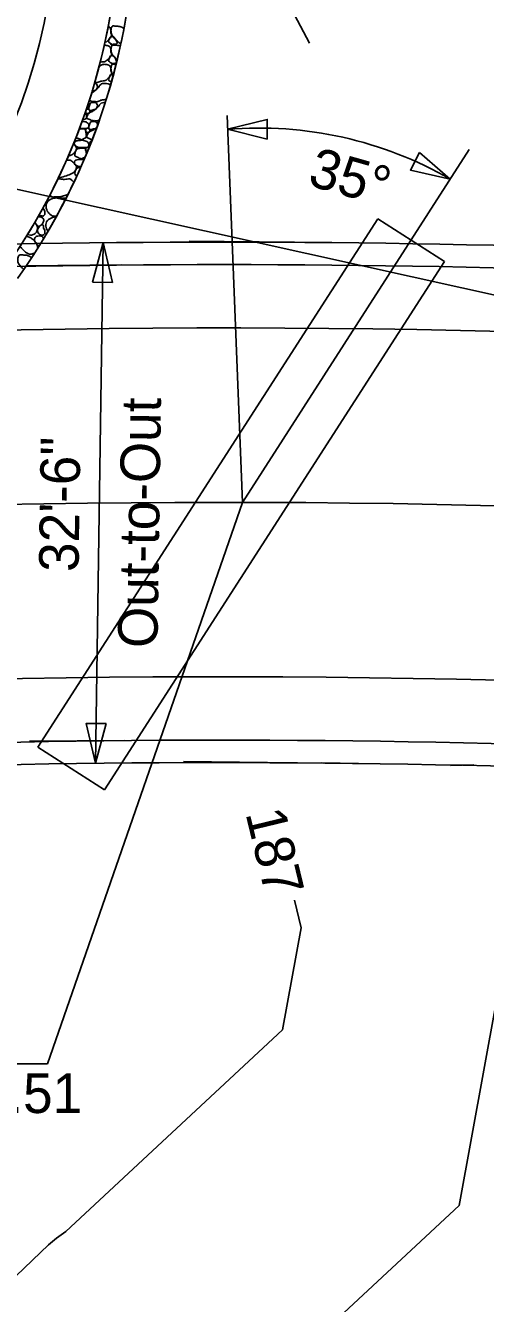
# Model space of a CAD drawing. Extents: x 1385284 to 1385995, y 1975154 to 1975620.
# Drawn here: x 1385501.9 to 1385530.9, y 1975439 to 1975519.6 of the extents above; entities that cross this region are included whole.
import ezdxf

# ---------------------------------------------------------------- set-up
doc = ezdxf.new("R2010")
doc.units = 0
for name, color, linetype in [('Default', 7, 'Continuous'), ('DTM_CONTOURS_MINOR', 7, 'Continuous'), ('R_Bridge', 7, 'Continuous'), ('R_Horz Alg', 7, 'Continuous'), ('R_Horz Alg Annot', 7, 'Continuous'), ('R_Proposed Const Limits', 7, 'Continuous'), ('R_Proposed Road', 7, 'Continuous')]:
    doc.layers.add(name, color=color, linetype=linetype)

msp = doc.modelspace()

# ---------------------------------------------------------------- linework, layer by layer
at = {"layer": 'Default'}
for p, q in [((1385514.615, 1975513.961), (1385515.576, 1975489.559)), ((1385515.576, 1975489.559), (1385529.884, 1975511.809)), ((1385502.679, 1975474.127), (1385524.111, 1975507.453)), ((1385524.111, 1975507.453), (1385528.316, 1975504.748)), ((1385506.801, 1975505.941), (1385506.327, 1975473.111)), ((1385521.062, 1975505.947), (1385512.231, 1975506.045)), ((1385507.954, 1975504.533), (1385501.951, 1975504.489)), ((1385506.884, 1975471.422), (1385528.316, 1975504.748)), ((1385515.576, 1975489.559), (1385503.294, 1975454.146)), ((1385508.172, 1975474.533), (1385502.168, 1975474.49)), ((1385502.679, 1975474.127), (1385506.884, 1975471.422)), ((1385520.694, 1975473.115), (1385511.864, 1975473.214)), ((1385522.895, 1975473.091), (1385520.589, 1975473.124)), ((1385530.16, 1975472.995), (1385528.688, 1975472.97)), ((1385503.294, 1975454.146), (1385480.831, 1975454.146))]:
    msp.add_line(p, q, dxfattribs=at)
for points in [[(1385517.149, 1975512.468), (1385514.649, 1975513.093), (1385517.149, 1975513.718)], [(1385526.741, 1975511.636), (1385528.686, 1975509.946), (1385526.175, 1975510.522)], [(1385506.14, 1975503.45), (1385506.801, 1975505.941), (1385507.39, 1975503.432)], [(1385506.988, 1975475.601), (1385506.327, 1975473.111), (1385505.739, 1975475.619)]]:
    msp.add_lwpolyline(points, close=True, dxfattribs=at)
for centre, radius, start, end in [((1385468.803, 1975526.863), 40, 324.56338, 101.99838), ((1385468.803, 1975526.863), 39, 324.56338, 101.99838), ((1385468.803, 1975526.863), 40, 324.56338, 46.11578), ((1385468.803, 1975526.863), 39, 324.56338, 45.8751), ((1385516.608, 1975488.949), 24.223, 60.09033, 94.63843)]:
    msp.add_arc(centre, radius, start, end, dxfattribs=at)
for points in [[(1385507.11, 1975519.581), (1385507.151, 1975519.575), (1385507.288, 1975519.487), (1385507.282, 1975519.271), (1385507.368, 1975518.96), (1385507.154, 1975518.753), (1385507.012, 1975518.6), (1385506.911, 1975518.569), (1385506.883, 1975518.563)], [(1385507.894, 1975518.503), (1385507.885, 1975518.508), (1385507.786, 1975518.568), (1385507.632, 1975518.71), (1385507.422, 1975518.934), (1385507.263, 1975519.174), (1385507.296, 1975519.4), (1385507.366, 1975519.642), (1385507.595, 1975519.589), (1385507.86, 1975519.595), (1385508.031, 1975519.509), (1385508.108, 1975519.463)], [(1385506.845, 1975518.391), (1385506.92, 1975518.401), (1385507.046, 1975518.381), (1385507.289, 1975518.296), (1385507.282, 1975518.068), (1385507.368, 1975517.757), (1385507.154, 1975517.55), (1385506.932, 1975517.327), (1385506.72, 1975517.351), (1385506.605, 1975517.315), (1385506.604, 1975517.315)], [(1385507.4, 1975518.447), (1385507.353, 1975518.446), (1385507.257, 1975518.519), (1385507.094, 1975518.612), (1385507.203, 1975518.797), (1385507.251, 1975518.962), (1385507.432, 1975518.936), (1385507.552, 1975518.831), (1385507.619, 1975518.687), (1385507.806, 1975518.438), (1385507.056, 1975518.455), (1385507.442, 1975518.444), (1385507.434, 1975518.447)], [(1385507.665, 1975517.481), (1385507.661, 1975517.486), (1385507.576, 1975517.57), (1385507.422, 1975517.731), (1385507.263, 1975517.971), (1385507.296, 1975518.197), (1385507.366, 1975518.439), (1385507.593, 1975518.387), (1385507.757, 1975518.383), (1385507.862, 1975518.363)], [(1385507.4, 1975517.244), (1385507.353, 1975517.243), (1385507.257, 1975517.316), (1385507.094, 1975517.409), (1385507.203, 1975517.594), (1385507.251, 1975517.759), (1385507.432, 1975517.733), (1385507.552, 1975517.628), (1385507.607, 1975517.496), (1385507.634, 1975517.399), (1385507.64, 1975517.37)], [(1385506.53, 1975516.983), (1385506.554, 1975517.017), (1385506.617, 1975517.119), (1385506.811, 1975517.205), (1385507.026, 1975517.179), (1385507.289, 1975517.093), (1385507.282, 1975516.865), (1385507.368, 1975516.554), (1385507.154, 1975516.347), (1385506.932, 1975516.124), (1385506.655, 1975516.157), (1385506.439, 1975516.005), (1385506.308, 1975516.04), (1385506.249, 1975516.045)], [(1385507.441, 1975516.535), (1385507.438, 1975516.537), (1385507.374, 1975516.623), (1385507.263, 1975516.768), (1385507.296, 1975516.994), (1385507.366, 1975517.236), (1385507.506, 1975517.19), (1385507.582, 1975517.186), (1385507.599, 1975517.186)], [(1385507.619, 1975517.273), (1385507.553, 1975517.246), (1385507.144, 1975517.25), (1385507.442, 1975517.241), (1385507.434, 1975517.244)], [(1385506.043, 1975515.366), (1385506.077, 1975515.378), (1385506.17, 1975515.437), (1385506.325, 1975515.561), (1385506.505, 1975515.703), (1385506.599, 1975515.909), (1385506.811, 1975516.002), (1385507.026, 1975515.976), (1385507.197, 1975515.955), (1385507.237, 1975515.895), (1385507.244, 1975515.883)], [(1385506.232, 1975515.99), (1385506.273, 1975515.986), (1385506.362, 1975515.968), (1385506.454, 1975515.865), (1385506.43, 1975515.705), (1385506.369, 1975515.588), (1385506.317, 1975515.558)], [(1385507.303, 1975516.078), (1385507.286, 1975516.088), (1385507.225, 1975516.135), (1385507.094, 1975516.206), (1385507.203, 1975516.391), (1385507.251, 1975516.556), (1385507.392, 1975516.549), (1385507.425, 1975516.53), (1385507.437, 1975516.522)], [(1385506.317, 1975515.558), (1385506.269, 1975515.543), (1385506.192, 1975515.524), (1385506.114, 1975515.506), (1385506.083, 1975515.499)], [(1385505.697, 1975514.219), (1385505.717, 1975514.171), (1385505.728, 1975514.048), (1385505.786, 1975513.785), (1385505.611, 1975513.712), (1385505.517, 1975513.668), (1385505.478, 1975513.649)], [(1385505.889, 1975514.089), (1385505.852, 1975514.089), (1385505.767, 1975514.087), (1385505.711, 1975514.152), (1385505.695, 1975514.197), (1385505.693, 1975514.209)], [(1385505.725, 1975514.313), (1385505.739, 1975514.331), (1385505.792, 1975514.384), (1385505.907, 1975514.338), (1385506.01, 1975514.178), (1385505.923, 1975514.118), (1385505.889, 1975514.089)], [(1385505.83, 1975514.661), (1385505.836, 1975514.656), (1385505.895, 1975514.601), (1385505.927, 1975514.513), (1385505.842, 1975514.352), (1385505.767, 1975514.354), (1385505.737, 1975514.355)], [(1385506.174, 1975513.635), (1385506.102, 1975513.63), (1385505.967, 1975513.71), (1385505.707, 1975513.799), (1385505.821, 1975513.968), (1385505.9, 1975514.155), (1385506.125, 1975514.199), (1385506.325, 1975514.358), (1385506.505, 1975514.5), (1385506.599, 1975514.706), (1385506.761, 1975514.773), (1385506.871, 1975514.786), (1385506.912, 1975514.787)], [(1385506.317, 1975514.355), (1385506.269, 1975514.34), (1385506.173, 1975514.317), (1385506.038, 1975514.263), (1385505.912, 1975514.305), (1385505.885, 1975514.411), (1385505.915, 1975514.525), (1385505.958, 1975514.652), (1385506.019, 1975514.777), (1385506.169, 1975514.793), (1385506.341, 1975514.789), (1385506.454, 1975514.662), (1385506.43, 1975514.502), (1385506.369, 1975514.385), (1385506.317, 1975514.355)], [(1385506.174, 1975514.838), (1385506.102, 1975514.833), (1385506.016, 1975514.878), (1385505.927, 1975514.925), (1385505.912, 1975514.933)], [(1385506.972, 1975514.983), (1385506.969, 1975514.982), (1385506.853, 1975514.93), (1385506.655, 1975514.954), (1385506.419, 1975514.778), (1385506.253, 1975514.858), (1385506.174, 1975514.838)], [(1385505.455, 1975513.589), (1385505.501, 1975513.587), (1385505.65, 1975513.58), (1385505.867, 1975513.496), (1385505.927, 1975513.31), (1385505.831, 1975513.144), (1385505.625, 1975513.151), (1385505.465, 1975513.146), (1385505.345, 1975513.152)], [(1385506.317, 1975513.152), (1385506.269, 1975513.137), (1385506.173, 1975513.114), (1385506.038, 1975513.06), (1385505.912, 1975513.102), (1385505.885, 1975513.208), (1385505.915, 1975513.322), (1385505.958, 1975513.449), (1385506.019, 1975513.574), (1385506.169, 1975513.59), (1385506.341, 1975513.586), (1385506.433, 1975513.481), (1385506.446, 1975513.412), (1385506.445, 1975513.379)], [(1385506.565, 1975513.692), (1385506.519, 1975513.673), (1385506.403, 1975513.583), (1385506.253, 1975513.655), (1385506.174, 1975513.635)], [(1385505.45, 1975512.432), (1385505.378, 1975512.442), (1385505.241, 1975512.507), (1385505.123, 1975512.549), (1385505.073, 1975512.595)], [(1385505.262, 1975513.087), (1385505.291, 1975513.097), (1385505.4, 1975513.128), (1385505.701, 1975513.135), (1385505.704, 1975512.893), (1385505.786, 1975512.582), (1385505.602, 1975512.504), (1385505.499, 1975512.456), (1385505.45, 1975512.432)], [(1385505.345, 1975513.152), (1385505.326, 1975513.144), (1385505.305, 1975513.142), (1385505.284, 1975513.144)], [(1385505.889, 1975512.886), (1385505.852, 1975512.886), (1385505.767, 1975512.884), (1385505.687, 1975512.965), (1385505.696, 1975513.083), (1385505.78, 1975513.185), (1385505.907, 1975513.135), (1385506.01, 1975512.975), (1385505.923, 1975512.915), (1385505.889, 1975512.886)], [(1385506.086, 1975512.444), (1385506.043, 1975512.457), (1385505.933, 1975512.522), (1385505.707, 1975512.596), (1385505.821, 1975512.765), (1385505.9, 1975512.952), (1385506.125, 1975512.996), (1385506.283, 1975513.119), (1385506.36, 1975513.193), (1385506.382, 1975513.214)], [(1385506.382, 1975513.215), (1385506.365, 1975513.19), (1385506.344, 1975513.167), (1385506.317, 1975513.152)], [(1385504.918, 1975512.193), (1385504.99, 1975512.128), (1385505.176, 1975511.991), (1385505.052, 1975511.634), (1385504.827, 1975511.472), (1385504.678, 1975511.418), (1385504.597, 1975511.391)], [(1385505.345, 1975511.949), (1385505.29, 1975511.925), (1385505.145, 1975511.983), (1385504.983, 1975512.069), (1385504.973, 1975512.236), (1385505.05, 1975512.367), (1385505.269, 1975512.386), (1385505.569, 1975512.416), (1385505.867, 1975512.293), (1385505.927, 1975512.107), (1385505.831, 1975511.941), (1385505.625, 1975511.948), (1385505.465, 1975511.943), (1385505.345, 1975511.949)], [(1385505.45, 1975511.229), (1385505.378, 1975511.239), (1385505.234, 1975511.308), (1385505.011, 1975511.379), (1385505.013, 1975511.607), (1385505.124, 1975511.853), (1385505.339, 1975511.902), (1385505.701, 1975511.932), (1385505.713, 1975511.734), (1385505.752, 1975511.618), (1385505.759, 1975511.595)], [(1385505.796, 1975511.691), (1385505.79, 1975511.693), (1385505.747, 1975511.706), (1385505.687, 1975511.762), (1385505.696, 1975511.88), (1385505.773, 1975511.972), (1385505.852, 1975511.955), (1385505.889, 1975511.933)], [(1385505.893, 1975511.943), (1385505.886, 1975511.956), (1385505.888, 1975512.017), (1385505.915, 1975512.119), (1385505.958, 1975512.246), (1385505.996, 1975512.329), (1385506.045, 1975512.359), (1385506.055, 1975512.363)], [(1385504.48, 1975511.143), (1385504.551, 1975511.143), (1385504.731, 1975511.191), (1385504.925, 1975510.996), (1385505.177, 1975510.792), (1385505.052, 1975510.431), (1385504.763, 1975510.241), (1385504.401, 1975510.142), (1385504.108, 1975510.039), (1385503.955, 1975510.027)], [(1385505.345, 1975510.746), (1385505.29, 1975510.722), (1385505.145, 1975510.78), (1385504.983, 1975510.866), (1385504.973, 1975511.033), (1385505.05, 1975511.164), (1385505.269, 1975511.183), (1385505.452, 1975511.192), (1385505.595, 1975511.169), (1385505.596, 1975511.169)], [(1385505.657, 1975511.329), (1385505.637, 1975511.319), (1385505.568, 1975511.286), (1385505.499, 1975511.253), (1385505.45, 1975511.229)], [(1385505.119, 1975510.154), (1385505.097, 1975510.168), (1385505.01, 1975510.227), (1385505.013, 1975510.404), (1385505.124, 1975510.65), (1385505.281, 1975510.687), (1385505.373, 1975510.716), (1385505.385, 1975510.72)], [(1385505.397, 1975510.744), (1385505.379, 1975510.744), (1385505.362, 1975510.745), (1385505.345, 1975510.746)], [(1385503.93, 1975509.974), (1385503.932, 1975509.974), (1385504.102, 1975509.967), (1385504.355, 1975509.905), (1385504.722, 1975509.998), (1385504.851, 1975509.849), (1385504.929, 1975509.777), (1385504.938, 1975509.769)], [(1385503.718, 1975507.624), (1385503.65, 1975507.59), (1385503.427, 1975507.727), (1385503.212, 1975507.972), (1385503.182, 1975508.49), (1385503.559, 1975508.746), (1385503.996, 1975508.775), (1385504.276, 1975508.744), (1385504.449, 1975508.737), (1385504.452, 1975508.737)], [(1385503.718, 1975508.827), (1385503.65, 1975508.793), (1385503.535, 1975508.863), (1385503.454, 1975508.932), (1385503.441, 1975508.944)], [(1385504.564, 1975508.975), (1385504.512, 1975508.958), (1385504.302, 1975508.905), (1385504.023, 1975508.809), (1385503.79, 1975508.824), (1385503.718, 1975508.827)], [(1385503.007, 1975508.172), (1385503.007, 1975508.168), (1385503.027, 1975508.104), (1385503.08, 1975507.995), (1385503.162, 1975507.859), (1385503.099, 1975507.755), (1385503.117, 1975507.725)], [(1385502.48, 1975507.234), (1385502.488, 1975507.226), (1385502.582, 1975507.118), (1385502.69, 1975506.95), (1385502.652, 1975506.633), (1385502.466, 1975506.46), (1385502.298, 1975506.416), (1385502.213, 1975506.417)], [(1385502.791, 1975506.991), (1385502.76, 1975506.917), (1385502.579, 1975507.076), (1385502.506, 1975507.197), (1385502.487, 1975507.247)], [(1385502.659, 1975507.551), (1385502.735, 1975507.574), (1385502.897, 1975507.575), (1385503.085, 1975507.452), (1385503.033, 1975507.214), (1385502.92, 1975507.049), (1385502.817, 1975507.001), (1385502.791, 1975506.991)], [(1385503.117, 1975506.522), (1385503.107, 1975506.497), (1385503.059, 1975506.407), (1385502.936, 1975506.422), (1385502.758, 1975506.441), (1385502.72, 1975506.557), (1385502.646, 1975506.666), (1385502.685, 1975506.83), (1385502.779, 1975506.942), (1385502.856, 1975507.03), (1385502.936, 1975507.086), (1385503.061, 1975507.035), (1385503.018, 1975506.918), (1385503.08, 1975506.792), (1385503.162, 1975506.656), (1385503.099, 1975506.552), (1385503.117, 1975506.522)], [(1385503.117, 1975507.725), (1385503.107, 1975507.7), (1385503.059, 1975507.61), (1385502.936, 1975507.625), (1385502.797, 1975507.63), (1385502.757, 1975507.689), (1385502.747, 1975507.708)], [(1385503.315, 1975506.679), (1385503.292, 1975506.71), (1385503.187, 1975506.868), (1385503.182, 1975507.287), (1385503.519, 1975507.525), (1385503.746, 1975507.562), (1385503.813, 1975507.567)], [(1385503.843, 1975507.619), (1385503.801, 1975507.62), (1385503.759, 1975507.622), (1385503.718, 1975507.624)], [(1385501.956, 1975506.339), (1385501.971, 1975506.337), (1385502.078, 1975506.32), (1385502.285, 1975506.217), (1385502.542, 1975506.006), (1385502.65, 1975505.78), (1385502.677, 1975505.64), (1385502.678, 1975505.619)], [(1385502.213, 1975506.417), (1385502.155, 1975506.414), (1385502.097, 1975506.434), (1385502.039, 1975506.465)], [(1385502.778, 1975505.771), (1385502.734, 1975505.737), (1385502.551, 1975505.903), (1385502.453, 1975506.074), (1385502.504, 1975506.294), (1385502.668, 1975506.367), (1385502.895, 1975506.374), (1385503.014, 1975506.279), (1385503.05, 1975506.215), (1385503.052, 1975506.212)], [(1385502.213, 1975505.214), (1385502.142, 1975505.211), (1385501.96, 1975505.295), (1385501.763, 1975505.477), (1385501.628, 1975505.63), (1385501.558, 1975505.726), (1385501.555, 1975505.73)], [(1385501.783, 1975504.262), (1385501.783, 1975504.262), (1385501.703, 1975504.342), (1385501.552, 1975504.498), (1385501.394, 1975504.738), (1385501.426, 1975504.964), (1385501.497, 1975505.206), (1385501.726, 1975505.154), (1385501.996, 1975505.159), (1385502.179, 1975505.065), (1385502.266, 1975505.01), (1385502.274, 1975505.006)], [(1385502.452, 1975505.276), (1385502.373, 1975505.233), (1385502.293, 1975505.213), (1385502.213, 1975505.214)]]:
    msp.add_open_spline(points, degree=3, dxfattribs=at)
at = {"layer": 'DTM_CONTOURS_MINOR'}
for points in [[(1385519.816, 1975518.527), (1385513.167, 1975531.095), (1385503.103, 1975535.092), (1385493.819, 1975536.129), (1385487.034, 1975541.44), (1385476.692, 1975537.174), (1385462.514, 1975531.326), (1385459.65, 1975533.856), (1385457.485, 1975537.268), (1385444.649, 1975523.958), (1385443.539, 1975522.941), (1385443.305, 1975522.664), (1385433.898, 1975513.612), (1385427.6, 1975506.926)], [(1385429.661, 1975380.205), (1385442.498, 1975392.558), (1385447.317, 1975399.181), (1385452.374, 1975404.141), (1385461.047, 1975414.424), (1385468.828, 1975419.202), (1385475.409, 1975426.871), (1385486.732, 1975431.928), (1385496.72, 1975436.365), (1385503.352, 1975442.717), (1385503.86, 1975443.147), (1385504.455, 1975443.576), (1385518.1, 1975456.293), (1385519.275, 1975462.722), (1385518.855, 1975464.457)], [(1385457.074, 1975380.205), (1385470.036, 1975391.55), (1385472.648, 1975393.763), (1385483.141, 1975404.025), (1385486.704, 1975407.042), (1385496.298, 1975416.333), (1385500.663, 1975420.022), (1385509.505, 1975428.49), (1385514.554, 1975432.762), (1385520.463, 1975437.019), (1385529.241, 1975445.201), (1385531.584, 1975458.02), (1385534.953, 1975460.368), (1385534.641, 1975463.628)]]:
    msp.add_lwpolyline(points, dxfattribs=at)
at = {"layer": 'R_Bridge'}
for radius, start, end in [(710.911, 84.79144, 93.554346), (709.494, 84.79144, 93.554346), (679.494, 86.221345, 95.633125), (678.078, 86.221345, 95.633125)]:
    msp.add_arc((1385514.357, 1974795.066), radius, start, end, dxfattribs=at)
at = {"layer": 'R_Horz Alg'}
msp.add_arc((1385514.357, 1974795.066), 694.494, 77.498258, 106.635112, dxfattribs=at)
at = {"layer": 'R_Horz Alg Annot'}
msp.add_line((1385315.54, 1975550.51), (1385664.693, 1975473.094), dxfattribs=at)
at = {"layer": 'R_Proposed Const Limits'}
msp.add_arc((1385468.803, 1975526.863), 35, 324.56338, 101.99838, dxfattribs=at)
at = {"layer": 'R_Proposed Road'}
for radius, end in [(705.494, 106.368381), (683.494, 106.910819)]:
    msp.add_arc((1385514.357, 1974795.066), radius, 77.498258, end, dxfattribs=at)

# ---------------------------------------------------------------- texts
at = {"layer": 'Default'}
for s, rotation, p in [('35%%d', 344.22069, (1385519.618, 1975509.585)), ('Out-to-Out', 89.17289, (1385510.224, 1975480.356)), ('32\'-6"', 89.17289, (1385505.251, 1975485.158)), ('187', 283.6099, (1385515.764, 1975469.951))]:
    msp.add_text(s, height=2.5, rotation=rotation, dxfattribs=at).set_placement(p)
msp.add_text('STA. 112+61.51', height=2.49999, dxfattribs=at).set_placement((1385481.22, 1975451.037))

doc.saveas('drawing.dxf')
